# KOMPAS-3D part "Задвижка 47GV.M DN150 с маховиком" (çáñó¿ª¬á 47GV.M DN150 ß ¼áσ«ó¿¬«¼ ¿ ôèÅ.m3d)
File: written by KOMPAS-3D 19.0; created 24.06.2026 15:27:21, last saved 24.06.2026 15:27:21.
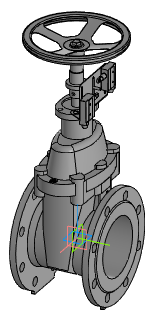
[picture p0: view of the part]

Document properties: Автор: Энергия; Полное имя файла: Z:\3.Личные\sachek\Dendor\3D для проектировщиков\2.7 Тип 47GV.M Задвижка клиновая фланцевая с обрезиненным клином\47GV.M DN150\Задвижка 47GV.M DN150 с маховиком.a3d

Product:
- Part/product: Задвижка 47GV.M DN150 с маховиком
    Масса: 53.6791
    source file: ..\47GV.M DN150\DR.47GVM.125.16.00.00 - Задвижка с обрезиненным клином DN125.spw
  - Component: Задвижка с обрезиненным клином DN125. Сборочный чертеж  | designation DR.47GVM.125.16.00.00СБ  | pos. 0  | Масса: 25.3494; Раздел спецификации: Документация; Форматы листов документа: 2xA3; source file: ..\47GV.M DN150\DR.47GVM.125.16.00.000 СБ - Задвижка с обрезиненным клином DN125.cdw

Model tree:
1. Операция без истории:1

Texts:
  Точка начала. Х
  Точка начала. Y
  Точка начала. Z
